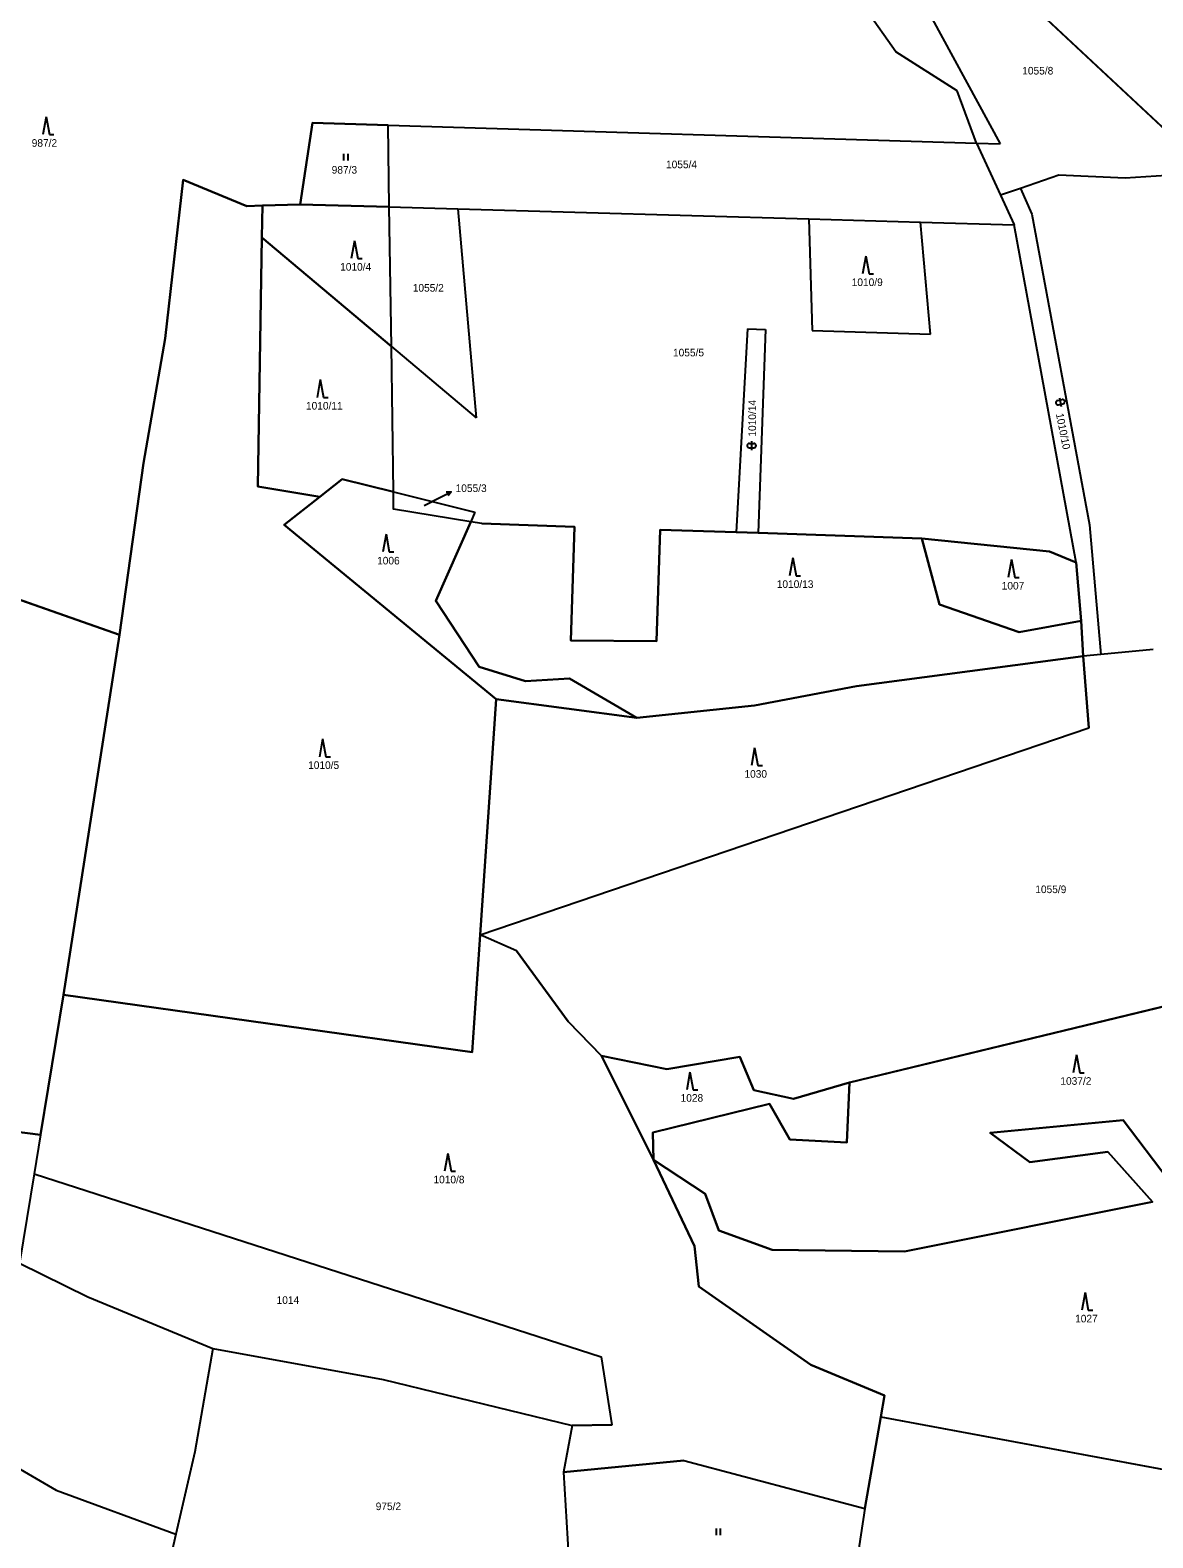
# Model space of a CAD drawing. Extents: x -760642 to -757221, y -1092371 to -1088855.
# Drawn here: x -759727.7 to -759476.2, y -1091216.8 to -1090879.2 of the extents above; entities that cross this region are included whole.
import ezdxf

# ---------------------------------------------------------------- set-up
doc = ezdxf.new("R2010")
doc.units = 0
for name, color, linetype in [('Vrstva 1', 7, 'Continuous'), ('Vrstva 16', 7, 'Continuous'), ('Vrstva 18', 7, 'Continuous'), ('Vrstva 25', 7, 'Continuous'), ('Vrstva 30', 7, 'Continuous')]:
    doc.layers.add(name, color=color, linetype=linetype)

msp = doc.modelspace()

# ---------------------------------------------------------------- linework, layer by layer
at = {"layer": 'Vrstva 1'}
for p, q in [((-759512.4, -1090865.14), (-759463.24, -1090911.1)), ((-759528.87, -1090870.74), (-759510.38, -1090904.72)), ((-759533.78, -1090884.07), (-759540.4, -1090874.66)), ((-759520.07, -1090892.82), (-759533.78, -1090884.07)), ((-759515.75, -1090904.56), (-759520.07, -1090892.82)), ((-759667.18, -1090918.25), (-759664.45, -1090900)), ((-759664.45, -1090900), (-759647.5, -1090900.52)), ((-759647.24, -1090918.82), (-759647.5, -1090900.52)), ((-759647.5, -1090900.52), (-759515.75, -1090904.56)), ((-759515.75, -1090904.56), (-759510.36, -1090916.2)), ((-759515.75, -1090904.56), (-759510.38, -1090904.72)), ((-759693.41, -1090912.72), (-759697.47, -1090948.3)), ((-759679.16, -1090918.62), (-759693.41, -1090912.72)), ((-759497.24, -1090911.74), (-759505.86, -1090914.67)), ((-759482.45, -1090912.4), (-759497.24, -1090911.74)), ((-759463.24, -1090911.1), (-759482.45, -1090912.4)), ((-759505.86, -1090914.67), (-759510.36, -1090916.2)), ((-759510.36, -1090916.2), (-759507.3, -1090922.8)), ((-759505.86, -1090914.67), (-759503.36, -1090920.44)), ((-759679.16, -1090918.62), (-759675.68, -1090918.51)), ((-759675.68, -1090918.51), (-759675.8, -1090925.65)), ((-759675.68, -1090918.51), (-759667.18, -1090918.25)), ((-759667.18, -1090918.25), (-759647.24, -1090918.82)), ((-759647.24, -1090918.82), (-759631.87, -1090919.26)), ((-759646.79, -1090950.06), (-759647.24, -1090918.82)), ((-759631.87, -1090919.26), (-759627.76, -1090966.07)), ((-759631.87, -1090919.26), (-759553.28, -1090921.49)), ((-759503.36, -1090920.44), (-759490.39, -1090990.02)), ((-759553.28, -1090921.49), (-759528.29, -1090922.2)), ((-759553.28, -1090921.49), (-759552.49, -1090946.52)), ((-759528.29, -1090922.2), (-759507.3, -1090922.8)), ((-759526, -1090947.28), (-759528.29, -1090922.2)), ((-759493.38, -1090998.4), (-759507.3, -1090922.8)), ((-759675.8, -1090925.65), (-759676.73, -1090981.41)), ((-759675.8, -1090925.65), (-759646.79, -1090950.06)), ((-759566.99, -1090946.11), (-759569.58, -1090991.66)), ((-759566.99, -1090946.11), (-759562.99, -1090946.23)), ((-759562.99, -1090946.23), (-759564.59, -1090991.83)), ((-759552.49, -1090946.52), (-759526, -1090947.28)), ((-759697.47, -1090948.3), (-759702.3, -1090976.2)), ((-759646.79, -1090950.06), (-759627.76, -1090966.07)), ((-759646.32, -1090982.65), (-759646.79, -1090950.06)), ((-759702.3, -1090976.2), (-759707.65, -1091014.61)), ((-759662.81, -1090983.72), (-759657.78, -1090979.8)), ((-759657.78, -1090979.8), (-759646.32, -1090982.65)), ((-759662.81, -1090983.72), (-759676.73, -1090981.41)), ((-759670.83, -1090989.98), (-759662.81, -1090983.72)), ((-759646.32, -1090982.65), (-759628.08, -1090987.19)), ((-759646.27, -1090986.47), (-759646.32, -1090982.65)), ((-759629.02, -1090989.33), (-759646.27, -1090986.47)), ((-759628.08, -1090987.19), (-759629.02, -1090989.33)), ((-759670.83, -1090989.98), (-759623.3, -1091029.04)), ((-759629.02, -1090989.33), (-759636.83, -1091007.02)), ((-759626.55, -1090989.74), (-759629.02, -1090989.33)), ((-759626.55, -1090989.74), (-759605.76, -1090990.44)), ((-759605.76, -1090990.44), (-759606.62, -1091015.93)), ((-759587.42, -1091016.08), (-759586.57, -1090991.09)), ((-759586.57, -1090991.09), (-759569.58, -1090991.66)), ((-759490.39, -1090990.02), (-759487.87, -1091019.06)), ((-759569.58, -1090991.66), (-759564.59, -1090991.83)), ((-759564.59, -1090991.83), (-759528, -1090993.07)), ((-759528, -1090993.07), (-759499.34, -1090995.94)), ((-759524.02, -1091007.85), (-759528, -1090993.07)), ((-759499.34, -1090995.94), (-759493.38, -1090998.4)), ((-759493.38, -1090998.4), (-759492.29, -1091011.53)), ((-759736.18, -1091004.6), (-759707.65, -1091014.61)), ((-759636.83, -1091007.02), (-759627.1, -1091021.81)), ((-759506.17, -1091014.06), (-759524.02, -1091007.85)), ((-759492.29, -1091011.53), (-759506.17, -1091014.06)), ((-759492.29, -1091011.53), (-759491.83, -1091019.41)), ((-759707.65, -1091014.61), (-759720.24, -1091095.27)), ((-759606.62, -1091015.93), (-759587.42, -1091016.08)), ((-759476.12, -1091017.93), (-759487.87, -1091019.06)), ((-759491.83, -1091019.41), (-759542.6, -1091026.14)), ((-759487.87, -1091019.06), (-759491.83, -1091019.41)), ((-759491.83, -1091019.41), (-759490.58, -1091035.45)), ((-759627.1, -1091021.81), (-759616.72, -1091025.02)), ((-759616.72, -1091025.02), (-759606.92, -1091024.42)), ((-759606.92, -1091024.42), (-759591.83, -1091033.22)), ((-759565.43, -1091030.48), (-759542.6, -1091026.14)), ((-759626.9, -1091081.81), (-759623.3, -1091029.04)), ((-759623.3, -1091029.04), (-759591.83, -1091033.22)), ((-759591.83, -1091033.22), (-759565.43, -1091030.48)), ((-759626.9, -1091081.81), (-759490.58, -1091035.45)), ((-759628.69, -1091108.09), (-759626.9, -1091081.81)), ((-759618.79, -1091085.39), (-759626.9, -1091081.81)), ((-759618.79, -1091085.39), (-759607.16, -1091101.24)), ((-759544.15, -1091114.84), (-759440.94, -1091089.89)), ((-759720.24, -1091095.27), (-759725.36, -1091126.58)), ((-759720.24, -1091095.27), (-759628.69, -1091108.09)), ((-759607.16, -1091101.24), (-759599.69, -1091108.89)), ((-759599.69, -1091108.89), (-759588.05, -1091132.18)), ((-759599.69, -1091108.89), (-759585.1, -1091111.85)), ((-759585.1, -1091111.85), (-759568.73, -1091109.12)), ((-759568.73, -1091109.12), (-759565.63, -1091116.61)), ((-759556.69, -1091118.55), (-759544.15, -1091114.84)), ((-759544.15, -1091114.84), (-759544.73, -1091128.33)), ((-759565.63, -1091116.61), (-759556.69, -1091118.55)), ((-759562.1, -1091119.66), (-759588.2, -1091126.04)), ((-759557.56, -1091127.66), (-759562.1, -1091119.66)), ((-759725.36, -1091126.58), (-759752.3, -1091123.16)), ((-759588.2, -1091126.04), (-759588.05, -1091132.18)), ((-759512.68, -1091126.11), (-759482.9, -1091123.3)), ((-759503.77, -1091132.7), (-759512.68, -1091126.11)), ((-759482.9, -1091123.3), (-759472.81, -1091136.57)), ((-759725.36, -1091126.58), (-759726.79, -1091135.31)), ((-759544.73, -1091128.33), (-759557.56, -1091127.66)), ((-759588.05, -1091132.18), (-759578.91, -1091151.5)), ((-759588.05, -1091132.18), (-759576.51, -1091139.8)), ((-759486.32, -1091130.37), (-759503.77, -1091132.7)), ((-759476.31, -1091141.59), (-759486.32, -1091130.37)), ((-759726.79, -1091135.31), (-759730.06, -1091155.33)), ((-759726.79, -1091135.31), (-759599.81, -1091176.28)), ((-759576.51, -1091139.8), (-759573.46, -1091147.97)), ((-759531.84, -1091152.72), (-759476.31, -1091141.59)), ((-759573.46, -1091147.97), (-759561.5, -1091152.36)), ((-759578.91, -1091151.5), (-759577.94, -1091160.53)), ((-759561.5, -1091152.36), (-759531.84, -1091152.72)), ((-759730.06, -1091155.33), (-759714.79, -1091162.83)), ((-759714.79, -1091162.83), (-759686.8, -1091174.41)), ((-759577.94, -1091160.53), (-759552.79, -1091178.09)), ((-759686.8, -1091174.41), (-759690.8, -1091197.56)), ((-759686.8, -1091174.41), (-759648.63, -1091181.37)), ((-759599.81, -1091176.28), (-759597.39, -1091191.48)), ((-759552.79, -1091178.09), (-759536.32, -1091184.92)), ((-759648.63, -1091181.37), (-759606.25, -1091191.66)), ((-759536.32, -1091184.92), (-759537.12, -1091189.76)), ((-759752.65, -1091188.34), (-759721.89, -1091206.11)), ((-759537.12, -1091189.76), (-759540.7, -1091210.22)), ((-759537.12, -1091189.76), (-759465.21, -1091203.12)), ((-759606.25, -1091191.66), (-759608.22, -1091202.14)), ((-759606.25, -1091191.66), (-759597.39, -1091191.48)), ((-759690.8, -1091197.56), (-759695.07, -1091215.98)), ((-759581.31, -1091199.49), (-759608.22, -1091202.14)), ((-759581.31, -1091199.49), (-759540.7, -1091210.22)), ((-759608.22, -1091202.14), (-759606.07, -1091238)), ((-759721.89, -1091206.11), (-759695.07, -1091215.98)), ((-759540.7, -1091210.22), (-759545.61, -1091242.47)), ((-759695.07, -1091215.98), (-759698.61, -1091231.29))]:
    msp.add_line(p, q, dxfattribs=at)
at = {"layer": 'Vrstva 16'}
for p, q in [((-759639.47, -1090985.66), (-759636.08, -1090983.98)), ((-759636.08, -1090983.98), (-759633.391, -1090982.649))]:
    msp.add_line(p, q, dxfattribs=at)
msp.add_lwpolyline([(-759634.509, -1090982.645), (-759633.391, -1090982.649), (-759634.066, -1090983.541)], dxfattribs=at)
at = {"layer": 'Vrstva 25'}
for p, q in [((-759724.122, -1090898.639), (-759724.855, -1090902.639)), ((-759724.122, -1090898.639), (-759723.389, -1090902.639)), ((-759723.389, -1090902.639), (-759722.389, -1090902.639)), ((-759657.507, -1090906.945), (-759657.507, -1090908.445)), ((-759656.485, -1090908.445), (-759656.485, -1090906.945)), ((-759655.052, -1090926.379), (-759655.785, -1090930.379)), ((-759655.052, -1090926.379), (-759654.319, -1090930.379)), ((-759654.319, -1090930.379), (-759653.319, -1090930.379)), ((-759540.512, -1090929.829), (-759541.245, -1090933.829)), ((-759540.512, -1090929.829), (-759539.779, -1090933.829)), ((-759539.779, -1090933.829), (-759538.779, -1090933.829)), ((-759662.702, -1090957.489), (-759663.435, -1090961.489)), ((-759662.702, -1090957.489), (-759661.969, -1090961.489)), ((-759661.969, -1090961.489), (-759660.969, -1090961.489)), ((-759497.538, -1090962.141), (-759496.558, -1090961.944)), ((-759497.341, -1090963.122), (-759496.361, -1090962.925)), ((-759497.146, -1090961.553), (-759496.753, -1090963.514)), ((-759566.59, -1090971.76), (-759565.59, -1090971.76)), ((-759566.59, -1090972.76), (-759565.59, -1090972.76)), ((-759566.09, -1090971.26), (-759566.09, -1090973.26)), ((-759647.982, -1090992.059), (-759648.715, -1090996.059)), ((-759647.982, -1090992.059), (-759647.249, -1090996.059)), ((-759647.249, -1090996.059), (-759646.249, -1090996.059)), ((-759556.872, -1090997.419), (-759557.605, -1091001.419)), ((-759556.872, -1090997.419), (-759556.139, -1091001.419)), ((-759507.892, -1090997.779), (-759508.625, -1091001.779)), ((-759507.892, -1090997.779), (-759507.159, -1091001.779)), ((-759556.139, -1091001.419), (-759555.139, -1091001.419)), ((-759507.159, -1091001.779), (-759506.159, -1091001.779)), ((-759662.182, -1091037.949), (-759662.915, -1091041.949)), ((-759662.182, -1091037.949), (-759661.449, -1091041.949)), ((-759661.449, -1091041.949), (-759660.449, -1091041.949)), ((-759565.412, -1091039.909), (-759566.145, -1091043.909)), ((-759565.412, -1091039.909), (-759564.679, -1091043.909)), ((-759564.679, -1091043.909), (-759563.679, -1091043.909)), ((-759493.332, -1091108.669), (-759494.065, -1091112.669)), ((-759493.332, -1091108.669), (-759492.599, -1091112.669)), ((-759579.892, -1091112.539), (-759580.625, -1091116.539)), ((-759579.892, -1091112.539), (-759579.159, -1091116.539)), ((-759492.599, -1091112.669), (-759491.599, -1091112.669)), ((-759579.159, -1091116.539), (-759578.159, -1091116.539)), ((-759634.122, -1091130.729), (-759634.855, -1091134.729)), ((-759634.122, -1091130.729), (-759633.389, -1091134.729)), ((-759633.389, -1091134.729), (-759632.389, -1091134.729)), ((-759491.412, -1091161.869), (-759492.145, -1091165.869)), ((-759491.412, -1091161.869), (-759490.679, -1091165.869)), ((-759490.679, -1091165.869), (-759489.679, -1091165.869)), ((-759574.047, -1091214.715), (-759574.047, -1091216.215)), ((-759573.025, -1091216.215), (-759573.025, -1091214.715))]:
    msp.add_line(p, q, dxfattribs=at)
for centre, start, end in [((-759497.44, -1090962.632), 101.35332, 281.35332), ((-759496.459, -1090962.435), 281.35332, 101.35332), ((-759566.59, -1090972.26), 90, 270), ((-759565.59, -1090972.26), 270, 90)]:
    msp.add_arc(centre, 0.5, start, end, dxfattribs=at)
at = {"layer": 'Vrstva 30'}
for points in [[(-759512.4, -1090865.14), (-759463.24, -1090911.1), (-759406.19, -1090909.28), (-759404.65, -1090913.58), (-759400.21, -1090912.96), (-759395.15, -1090909.74), (-759380.59, -1090895.02), (-759393.62, -1090856.53), (-759451.63, -1090844.46), (-759512.4, -1090865.14)], [(-759736.18, -1091004.6), (-759707.65, -1091014.61), (-759702.3, -1090976.2), (-759697.47, -1090948.3), (-759693.41, -1090912.72), (-759679.16, -1090918.62), (-759675.68, -1090918.51), (-759667.18, -1090918.25), (-759664.45, -1090900), (-759647.5, -1090900.52), (-759515.75, -1090904.56), (-759520.07, -1090892.82), (-759533.78, -1090884.07), (-759540.4, -1090874.66)], [(-759647.5, -1090900.52), (-759664.45, -1090900), (-759667.18, -1090918.25), (-759647.24, -1090918.82), (-759647.5, -1090900.52)], [(-759676.73, -1090981.41), (-759675.8, -1090925.65), (-759675.68, -1090918.51), (-759679.16, -1090918.62), (-759693.41, -1090912.72), (-759697.47, -1090948.3), (-759702.3, -1090976.2), (-759707.65, -1091014.61), (-759720.24, -1091095.27), (-759628.69, -1091108.09), (-759626.9, -1091081.81), (-759623.3, -1091029.04), (-759670.83, -1090989.98), (-759662.81, -1090983.72), (-759676.73, -1090981.41)], [(-759675.8, -1090925.65), (-759646.79, -1090950.06), (-759647.24, -1090918.82), (-759667.18, -1090918.25), (-759675.68, -1090918.51), (-759675.8, -1090925.65)], [(-759657.78, -1090979.8), (-759646.32, -1090982.65), (-759646.79, -1090950.06), (-759675.8, -1090925.65), (-759676.73, -1090981.41), (-759662.81, -1090983.72), (-759657.78, -1090979.8)], [(-759657.78, -1090979.8), (-759662.81, -1090983.72), (-759670.83, -1090989.98), (-759623.3, -1091029.04), (-759591.83, -1091033.22), (-759606.92, -1091024.42), (-759616.72, -1091025.02), (-759627.1, -1091021.81), (-759636.83, -1091007.02), (-759629.02, -1090989.33), (-759646.27, -1090986.47), (-759646.32, -1090982.65), (-759657.78, -1090979.8)], [(-759707.65, -1091014.61), (-759736.18, -1091004.6), (-759753.33, -1091001.99), (-759778.18, -1091009.55), (-759806.76, -1091002.37), (-759808.17, -1091011.49), (-759828.7, -1091004.09), (-759865.02, -1090987.83), (-759871.7, -1091031.3), (-759881.35, -1091075.16), (-759839.95, -1091081.59), (-759822.78, -1091091.41), (-759808.66, -1091098.94), (-759794.02, -1091105.38), (-759764.23, -1091118.06), (-759752.3, -1091123.16), (-759725.36, -1091126.58), (-759720.24, -1091095.27), (-759707.65, -1091014.61)], [(-759506.17, -1091014.06), (-759524.02, -1091007.85), (-759528, -1090993.07), (-759564.59, -1090991.83), (-759569.58, -1090991.66), (-759586.57, -1090991.09), (-759587.42, -1091016.08), (-759606.62, -1091015.93), (-759605.76, -1090990.44), (-759626.55, -1090989.74), (-759629.02, -1090989.33), (-759636.83, -1091007.02), (-759627.1, -1091021.81), (-759616.72, -1091025.02), (-759606.92, -1091024.42), (-759591.83, -1091033.22), (-759565.43, -1091030.48), (-759542.6, -1091026.14), (-759491.83, -1091019.41), (-759492.29, -1091011.53), (-759506.17, -1091014.06)], [(-759528, -1090993.07), (-759524.02, -1091007.85), (-759506.17, -1091014.06), (-759492.29, -1091011.53), (-759493.38, -1090998.4), (-759499.34, -1090995.94), (-759528, -1090993.07)], [(-759491.83, -1091019.41), (-759542.6, -1091026.14), (-759565.43, -1091030.48), (-759591.83, -1091033.22), (-759623.3, -1091029.04), (-759626.9, -1091081.81), (-759490.58, -1091035.45), (-759491.83, -1091019.41)], [(-759606.25, -1091191.66), (-759608.22, -1091202.14), (-759581.31, -1091199.49), (-759540.7, -1091210.22), (-759537.12, -1091189.76), (-759536.32, -1091184.92), (-759552.79, -1091178.09), (-759577.94, -1091160.53), (-759578.91, -1091151.5), (-759588.05, -1091132.18), (-759599.69, -1091108.89), (-759607.16, -1091101.24), (-759618.79, -1091085.39), (-759626.9, -1091081.81), (-759628.69, -1091108.09), (-759720.24, -1091095.27), (-759725.36, -1091126.58), (-759726.79, -1091135.31), (-759599.81, -1091176.28), (-759597.39, -1091191.48), (-759606.25, -1091191.66)], [(-759588.2, -1091126.04), (-759588.05, -1091132.18), (-759576.51, -1091139.8), (-759573.46, -1091147.97), (-759561.5, -1091152.36), (-759531.84, -1091152.72), (-759476.31, -1091141.59), (-759486.32, -1091130.37), (-759503.77, -1091132.7), (-759512.68, -1091126.11), (-759482.9, -1091123.3), (-759472.81, -1091136.57), (-759454.25, -1091137.91), (-759440.83, -1091148.4), (-759418.62, -1091137.45), (-759421.13, -1091116.83), (-759425.18, -1091105.54), (-759451.26, -1091105.65), (-759440.94, -1091089.89), (-759544.15, -1091114.84), (-759544.73, -1091128.33), (-759557.56, -1091127.66), (-759562.1, -1091119.66), (-759588.2, -1091126.04)], [(-759562.1, -1091119.66), (-759557.56, -1091127.66), (-759544.73, -1091128.33), (-759544.15, -1091114.84), (-759556.69, -1091118.55), (-759565.63, -1091116.61), (-759568.73, -1091109.12), (-759585.1, -1091111.85), (-759599.69, -1091108.89), (-759588.05, -1091132.18), (-759588.2, -1091126.04), (-759562.1, -1091119.66)], [(-759472.81, -1091136.57), (-759482.9, -1091123.3), (-759512.68, -1091126.11), (-759503.77, -1091132.7), (-759486.32, -1091130.37), (-759476.31, -1091141.59), (-759531.84, -1091152.72), (-759561.5, -1091152.36), (-759573.46, -1091147.97), (-759576.51, -1091139.8), (-759588.05, -1091132.18), (-759578.91, -1091151.5), (-759577.94, -1091160.53), (-759552.79, -1091178.09), (-759536.32, -1091184.92), (-759537.12, -1091189.76), (-759465.21, -1091203.12)]]:
    msp.add_lwpolyline(points, dxfattribs=at)

# ---------------------------------------------------------------- texts
at = {"layer": 'Vrstva 16'}
msp.add_text('1055/3', height=1.7, dxfattribs=at).set_placement((-759632.39, -1090982.65))
at = {"layer": 'Vrstva 18'}
for s, height, p in [('1055/8', 1.7, (-759505.47, -1090889.17)), ('987/2', 1.7, (-759727.342, -1090905.35)), ('987/3', 1.7, (-759660.15, -1090911.37)), ('1055/4', 1.7, (-759585.26, -1090910.16)), ('1010/4', 1.7, (-759658.26, -1090933.09)), ('1055/2', 1.7, (-759641.99, -1090937.79)), ('1010/9', 1.7, (-759543.67, -1090936.53)), ('1055/5', 1.7, (-759583.7, -1090952.28)), ('1010/11', 1.7, (-759665.91, -1090964.2)), ('1055/3', 0.1, (-759639.634, -1090985.66)), ('1006', 1.7, (-759649.98, -1090998.87)), ('1010/13', 1.7, (-759560.46, -1091004.13)), ('1007', 1.7, (-759510.07, -1091004.49)), ('1010/5', 1.7, (-759665.432, -1091044.66)), ('1030', 1.7, (-759567.699, -1091046.62)), ('1055/9', 1.7, (-759502.55, -1091072.46)), ('1037/2', 1.7, (-759496.93, -1091115.38)), ('1028', 1.7, (-759582, -1091119.17)), ('1010/8', 1.7, (-759637.358, -1091137.44)), ('1014', 1.7, (-759672.49, -1091164.43)), ('1027', 1.7, (-759493.63, -1091168.58)), ('975/2', 1.7, (-759650.29, -1091210.61))]:
    msp.add_text(s, height=height, dxfattribs=at).set_placement(p)
for s, rotation, p in [('1010/14', 90, (-759565.11, -1090970.26)), ('1010/10', 281.35332, (-759497.94, -1090965.18))]:
    msp.add_text(s, height=1.7, rotation=rotation, dxfattribs=at).set_placement(p)

doc.saveas('drawing.dxf')
